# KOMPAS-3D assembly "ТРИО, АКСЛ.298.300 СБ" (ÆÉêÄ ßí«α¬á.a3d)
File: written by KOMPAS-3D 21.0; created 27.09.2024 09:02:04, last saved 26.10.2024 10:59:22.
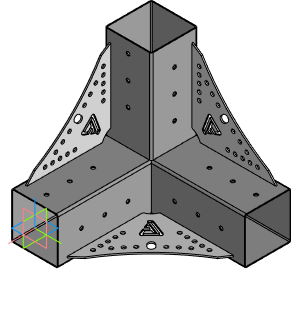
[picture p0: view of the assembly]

Document properties: Полное имя файла: C:\Users\79253\YandexDisk\Соединения бруса\Соединения бруса\ТРИО\ТРИО сборка.a3d; Автор: Алексей Бочаров

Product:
- Part/product: ТРИО  | designation АКСЛ.298.300 СБ
    Масса: 5.166365
    source file: АКСЛ.298.300 - ТРИО.spw, ТРИО спецификация.spw
  - Component [assembly]: Перемычка  | designation АКСЛ.298.201  | qty 3  | pos. 1  | Масса: 0.308618; source file: ..\Перемычка.stp
  - Component [detail]: Профиль L = 200 мм  | designation АКСЛ.298.301  | pos. 2  | Масса: 1.210897; Форматы листов документа: A2; source file: АКСЛ.298.301 - Профиль L = 200 мм.cdw, Профиль L = 200 мм.m3d
  - Component [detail]: Профиль L = 300 мм  | designation АКСЛ.298.302-01  | pos. 4  | Масса: 1.514806; source file: АКСЛ.298.302-01 - Профиль L = 300 мм.cdw, Профиль L = 300 мм (2).m3d
  - Component [detail]: Профиль L = 300 мм  | designation АКСЛ.298.302  | pos. 3  | Масса: 1.514806; Форматы листов документа: A2; source file: АКСЛ.298.302 - Профиль L = 300 мм.cdw, Профиль L = 300 мм (1).m3d

Referenced files in C:\Users\79253\YandexDisk\Соединения бруса\Соединения бруса\ТРИО\: Профиль L = 300 мм (1).m3d, Профиль L = 300 мм (2).m3d, Профиль L = 200 мм.m3d
Referenced files: АКСЛ.298.300 СБ>Деталь (локальная).m3d
Referenced files in C:\Users\79253\YandexDisk\Соединения бруса\Соединения бруса\: Перемычка.stp
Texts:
  АКСЛ.298.300 СБ
  АКСЛ.298.302 Профиль L = 300 мм
  АКСЛ.298.302-01 Профиль L = 300 мм
  АКСЛ.298.301 Профиль L = 200 мм
  АКСЛ.298.201 Перемычка (1)
  АКСЛ.298.201 Перемычка (2)
  АКСЛ.298.201 Перемычка (3)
